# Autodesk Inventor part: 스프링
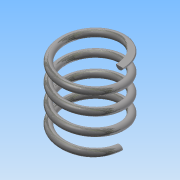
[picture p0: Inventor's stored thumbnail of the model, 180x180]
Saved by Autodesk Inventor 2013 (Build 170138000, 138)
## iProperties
Created: 2017-07
Part Number: 스프링
Material: 스테인리스강
Document SubType Name: Modeling
Designer: Administrator
Mass: 5.31051 g
Surface Area: 13.3828 cm^2
Volume: 0.657241 cm^3
Density: 8.08 g/cm^3
Author: Administrator
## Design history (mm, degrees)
sketch "스케치2"
  geometry: L1 (0, 0)-(-8.5, 0); L2 (-8.5, 0)-(-8.5, -20.5); L3 (-8.5, -20.5)-(0, -20.5); L4 (0, -20.5)-(0, 0); C1 r 1 at (-8.5, 0)
  constraints: 8 end point, 2 parallel, 1 centre point, 1 coincident, 1 horizontal, 1 perpendicular
  dimensions: "d0" = 2 diameter of C1; "d2" = 20.5 distance of L1.end L2.end (derived); "d3" = 17 diameter of L2 L4
feature "코일1" pitch "d4" = 10; turns "d6" = 4; dims "d5" = 20.5 (= d2), "d7" = 0, angle "d8" = 90 deg, angle "d9" = 90 deg, "d10" = 0, "d11" = 0
sketch "스케치3"
  geometry: L1 (9.5, 0)-(7.5, 0) reference; 1 further point
  constraints: 1 horizontal alignment
extrude "돌출1" cut sketch "스케치3" stored distance "d12" = 10; taper "d13" = 0 deg
node "작업 평면1"
sketch "스케치4"
  geometry: L1 (-1, 0)-(1, 0) reference; 1 further point
  constraints: 1 horizontal alignment
extrude "돌출2" cut sketch "스케치4" stored distance "d15" = 10; taper "d16" = 0 deg
node "솔리드1"
node "절단 모서리 투영1"
node "절단 모서리 투영2"
other parameters: "d14" = 90 deg
